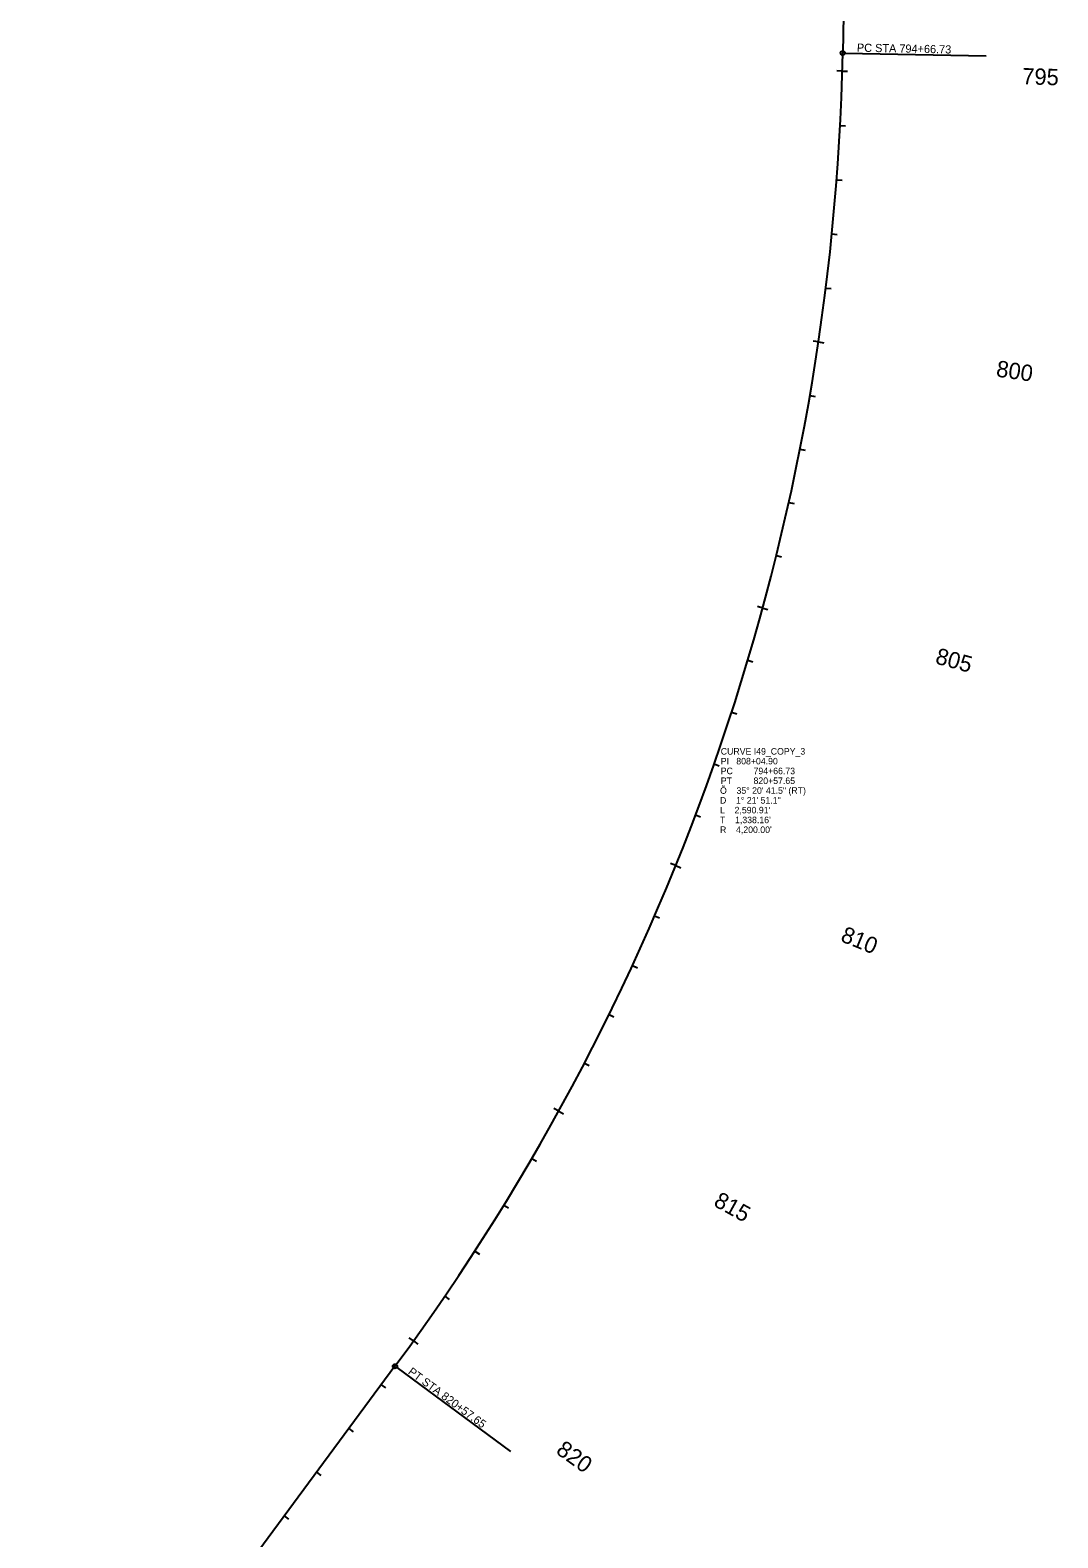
# Model space of a CAD drawing. Extents: x 2820825 to 2825694, y 116785 to 142398.
# Drawn here: x 2822208 to 2824096, y 136679 to 139451 of the extents above; entities that cross this region are included whole.
import ezdxf

# ---------------------------------------------------------------- set-up
doc = ezdxf.new("R2010")
doc.units = 0
for name, color, linetype in [('Default', 7, 'Continuous'), ('Roadway-Centerline main', 7, 'Continuous'), ('Roadway-Curve pc pt', 7, 'Continuous'), ('Text-Curve info', 7, 'Continuous')]:
    doc.layers.add(name, color=color, linetype=linetype)

msp = doc.modelspace()

# ---------------------------------------------------------------- linework, layer by layer
at = {"layer": 'Default'}
msp.add_line((2822878.3, 136994.9), (2822207.8, 136088.7), dxfattribs=at)
msp.add_arc((2819501.9, 139492.9), 4200, 323.5041, 358.849, dxfattribs=at)
at = {"layer": 'Roadway-Centerline main'}
for p, q in [((2823760.8, 142380.9), (2823701.1, 139408.5)), ((2823700.3, 139375.3), (2823690.3, 139375.6)), ((2823700.3, 139375.3), (2823710.2, 139375)), ((2823696.3, 139275.4), (2823706.2, 139274.9)), ((2823689.9, 139175.6), (2823699.9, 139174.8)), ((2823681.2, 139076), (2823691.1, 139075)), ((2823670, 138976.6), (2823680, 138975.4)), ((2823656.6, 138877.5), (2823646.7, 138879)), ((2823656.6, 138877.5), (2823666.5, 138876)), ((2823640.7, 138778.8), (2823650.6, 138777.1)), ((2823622.6, 138680.4), (2823632.4, 138678.5)), ((2823602.1, 138582.6), (2823611.8, 138580.4)), ((2823579.2, 138485.2), (2823588.9, 138482.8)), ((2823554.1, 138388.4), (2823544.4, 138391)), ((2823554.1, 138388.4), (2823563.7, 138385.8)), ((2823526.6, 138292.3), (2823536.2, 138289.4)), ((2823496.9, 138196.8), (2823506.4, 138193.7)), ((2823464.9, 138102), (2823474.3, 138098.7)), ((2823430.7, 138008.1), (2823440, 138004.5)), ((2823394.2, 137915), (2823384.9, 137918.7)), ((2823394.2, 137915), (2823403.5, 137911.2)), ((2823355.5, 137822.8), (2823364.7, 137818.8)), ((2823314.7, 137731.5), (2823323.8, 137727.3)), ((2823271.7, 137641.2), (2823280.6, 137636.8)), ((2823226.5, 137552), (2823235.4, 137547.4)), ((2823179.3, 137463.9), (2823170.5, 137468.7)), ((2823179.3, 137463.9), (2823188, 137459)), ((2823129.9, 137376.9), (2823138.5, 137371.9)), ((2823078.5, 137291.1), (2823087, 137285.9)), ((2823025.1, 137206.6), (2823033.5, 137201.1)), ((2822969.6, 137123.4), (2822977.9, 137117.7)), ((2822912.2, 137041.5), (2822904.1, 137047.3)), ((2822912.2, 137041.5), (2822920.4, 137035.6)), ((2822878.3, 136994.9), (2822207.8, 136088.7)), ((2822853.1, 136960.9), (2822861.1, 136954.9)), ((2822793.6, 136880.5), (2822801.6, 136874.5)), ((2822734.1, 136800.1), (2822742.2, 136794.1)), ((2822674.7, 136719.7), (2822682.7, 136713.7))]:
    msp.add_line(p, q, dxfattribs=at)
msp.add_arc((2819501.9, 139492.9), 4200, 323.5041, 358.849, dxfattribs=at)
at = {"layer": 'Roadway-Curve pc pt'}
for p, q in [((2823705.1, 139408.5), (2823964.7, 139403.2)), ((2822881.5, 136992.5), (2823090.3, 136838))]:
    msp.add_line(p, q, dxfattribs=at)
for centre in [(2823701.1, 139408.5), (2822878.3, 136994.9)]:
    msp.add_circle(centre, 4, dxfattribs=at)

# ---------------------------------------------------------------- texts
at = {"layer": 'Roadway-Centerline main'}
for s, rotation, p in [(' 795', 358.3951, (2824019.7, 139351.3)), (' 800', 351.5742, (2823970.9, 138815.8)), (' 805', 344.7533, (2823858.9, 138289.8)), (' 810', 337.9324, (2823685.1, 137780.8)), (' 815', 331.1114, (2823452.2, 137296.1)), (' 820', 324.2905, (2823163.3, 136842.5))]:
    msp.add_text(s, height=30, rotation=rotation, dxfattribs=at).set_placement(p)
at = {"layer": 'Roadway-Curve pc pt'}
for s, rotation, p in [('PC STA 794+66.73', 358.849, (2823727.1, 139411)), ('PT STA 820+57.65', 323.5041, (2822901, 136981.9))]:
    msp.add_text(s, height=15, rotation=rotation, dxfattribs=at).set_placement(p)
at = {"layer": 'Text-Curve info'}
for s, p in [('CURVE I49_COPY_3', (2823477, 138119)), ('PI   808+04.90', (2823477, 138101)), ('PC', (2823477, 138083)), ('794+66.73', (2823537.2, 138083)), ('Õ    35%%d 20\' 41.5" (RT)', (2823475.6, 138047)), ('PT', (2823477, 138065)), ('820+57.65', (2823537.2, 138065)), ('D    1%%d 21\' 51.1"', (2823475.6, 138029)), ("T    1,338.16'", (2823475.6, 137993)), ("L    2,590.91'", (2823475.6, 138011)), ("R    4,200.00'", (2823475.6, 137975))]:
    msp.add_text(s, height=12, dxfattribs=at).set_placement(p)

doc.saveas('drawing.dxf')
